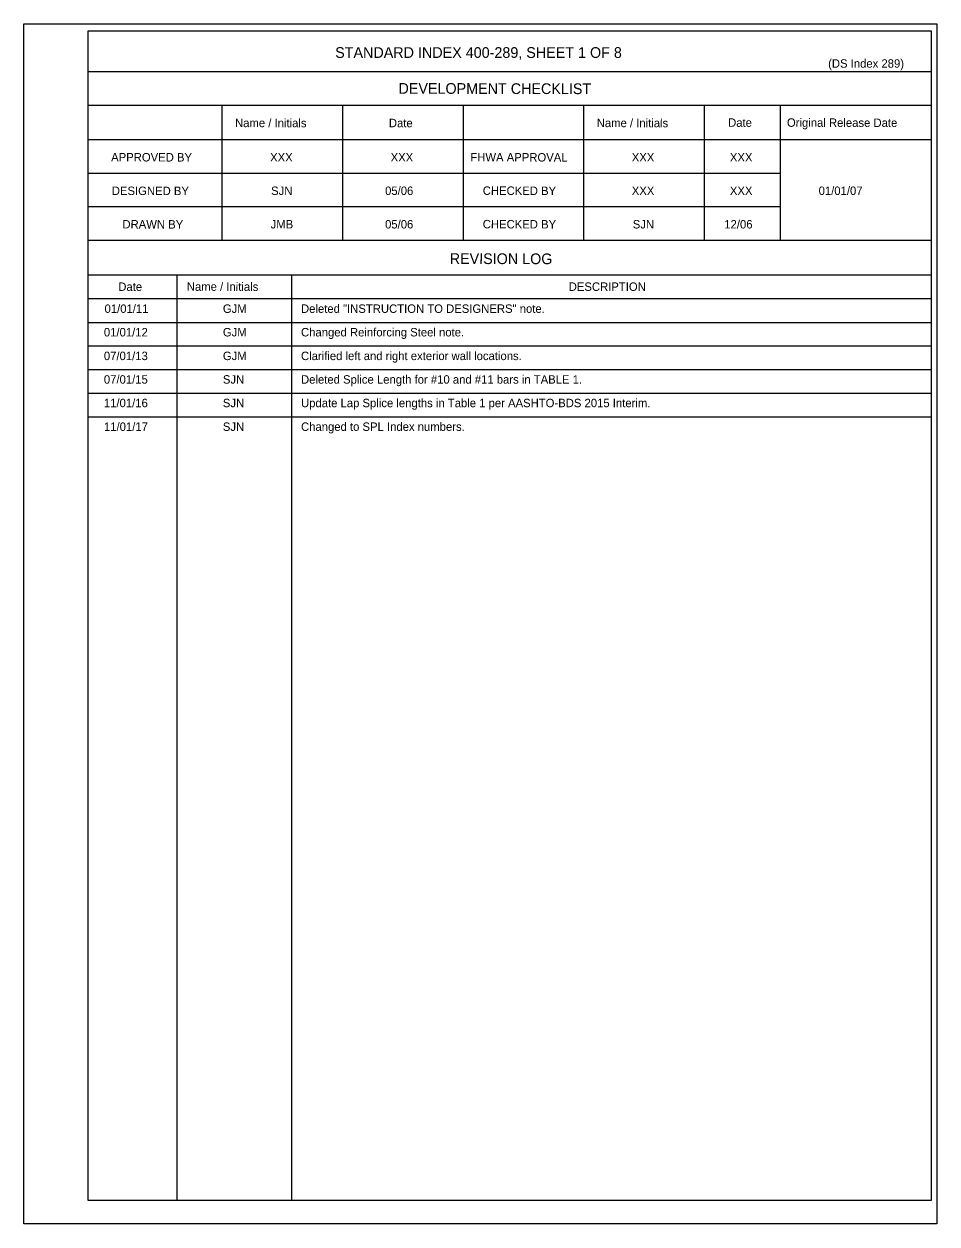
# Model space of a CAD drawing. Extents: x 6 to 291, y -45 to 111.
# Drawn here: x 209.7 to 291.5, y -6 to 101.5 of the extents above; entities that cross this region are included whole.
import ezdxf

# ---------------------------------------------------------------- set-up
doc = ezdxf.new("R2010")
doc.units = 0
for name, color, linetype in [('AdhocPoint_dp', 7, 'Continuous'), ('Patterning', 7, 'Continuous'), ('PlotBorder_dp', 7, 'Continuous'), ('TextMisc', 7, 'Continuous')]:
    doc.layers.add(name, color=color, linetype=linetype)

msp = doc.modelspace()

# ---------------------------------------------------------------- linework, layer by layer
at = {"layer": 'Patterning'}
msp.add_line((209.68, -6.02), (209.68, -6.02), dxfattribs=at)
msp.add_lwpolyline([(209.68, 101.47), (291.47, 101.47), (291.47, -6.02), (209.68, -6.02)], close=True, dxfattribs=at)
at = {"layer": 'PlotBorder_dp'}
for p, q in [((215.42, 74.74), (290.96, 74.74)), ((215.42, 72.63), (290.96, 72.63)), ((215.42, 70.52), (290.96, 70.52)), ((215.42, 68.4), (290.96, 68.4)), ((215.42, 66.29), (290.96, 66.29))]:
    msp.add_line(p, q, dxfattribs=at)
at = {"layer": 'TextMisc'}
for p, q in [((290.96, 97.18), (215.42, 97.18)), ((290.96, 94.18), (215.42, 94.18)), ((227.42, 94.18), (227.42, 82.08)), ((238.22, 94.18), (238.22, 82.08)), ((249.02, 94.18), (249.02, 82.08)), ((259.82, 94.18), (259.82, 82.08)), ((270.62, 94.18), (270.62, 82.08)), ((277.42, 94.18), (277.42, 82.08)), ((290.96, 91.08), (215.42, 91.08)), ((277.42, 88.08), (215.42, 88.08)), ((277.42, 85.08), (215.42, 85.08)), ((290.96, 82.08), (215.42, 82.08)), ((290.96, 78.97), (215.42, 78.97)), ((223.37, 78.97), (223.37, -3.92)), ((233.65, 78.97), (233.65, -3.92)), ((290.96, 76.86), (215.42, 76.86))]:
    msp.add_line(p, q, dxfattribs=at)
msp.add_lwpolyline([(215.42, 100.86), (290.96, 100.86), (290.96, -3.92), (215.42, -3.92)], close=True, dxfattribs=at)

# ---------------------------------------------------------------- texts
at = {"layer": 'AdhocPoint_dp'}
for s, height, p in [('STANDARD INDEX 400-289, SHEET 1 OF 8', 0.9599, (237.56, 98.43)), ('(DS Index 289)', 0.756, (281.72, 97.55)), ('XXX', 0.756, (231.73, 89.15)), ('XXX', 0.756, (242.53, 89.15)), ('XXX', 0.756, (264.13, 89.15)), ('XXX', 0.756, (272.92, 89.15)), ('SJN', 0.756, (231.82, 86.15)), ('05/06', 0.756, (242.03, 86.15)), ('XXX', 0.756, (264.13, 86.15)), ('XXX', 0.756, (272.92, 86.15)), ('01/01/07', 0.756, (280.87, 86.15)), ('JMB', 0.756, (231.78, 83.15)), ('05/06', 0.756, (242.03, 83.15)), ('SJN', 0.756, (264.22, 83.15)), ('12/06', 0.756, (272.42, 83.15)), ('DESCRIPTION', 0.7559, (258.48, 77.56)), ('01/01/11', 0.756, (216.9, 75.59)), ('GJM', 0.756, (227.5, 75.59)), ('Deleted "INSTRUCTION TO DESIGNERS" note.', 0.756, (234.5, 75.59)), ('01/01/12', 0.756, (216.84, 73.48)), ('GJM', 0.756, (227.5, 73.48)), ('Changed Reinforcing Steel note.', 0.756, (234.5, 73.48)), ('07/01/13', 0.756, (216.84, 71.36)), ('GJM', 0.756, (227.5, 71.36)), ('Clarified left and right exterior wall locations.', 0.756, (234.5, 71.36)), ('07/01/15', 0.756, (216.84, 69.25)), ('SJN', 0.756, (227.5, 69.25)), ('Deleted Splice Length for #10 and #11 bars in TABLE 1.', 0.756, (234.5, 69.25)), ('11/01/16', 0.756, (216.84, 67.14)), ('SJN', 0.756, (227.5, 67.14)), ('Update Lap Splice lengths in Table 1 per AASHTO-BDS 2015 Interim.', 0.756, (234.5, 67.14)), ('11/01/17', 0.756, (216.85, 65.02)), ('SJN', 0.756, (227.5, 65.02)), ('Changed to SPL Index numbers.', 0.756, (234.5, 65.02))]:
    msp.add_text(s, height=height, dxfattribs=at).set_placement(p)
for s, height, p in [('DEVELOPMENT CHECKLIST', 0.9599, (243.23, 95.22)), ('Name / Initials', 0.7559, (228.59, 92.23)), ('Date', 0.756, (242.37, 92.22)), ('Name / Initials', 0.7559, (260.99, 92.23)), ('Date', 0.756, (272.76, 92.26)), ('Original Release Date', 0.7559, (278.03, 92.26)), ('APPROVED BY', 0.7559, (217.49, 89.16)), ('FHWA APPROVAL', 0.7559, (249.67, 89.16)), ('DESIGNED BY', 0.7559, (217.55, 86.15)), ('CHECKED BY', 0.756, (250.78, 86.16)), ('DRAWN BY', 0.756, (218.5, 83.15)), ('CHECKED BY', 0.756, (250.78, 83.16)), ('REVISION LOG', 0.9599, (247.82, 79.97)), ('Date', 0.756, (218.13, 77.56)), ('Name / Initials', 0.7559, (224.27, 77.57))]:
    msp.add_text(s, height=height, rotation=359.8756, dxfattribs=at).set_placement(p)

doc.saveas('drawing.dxf')
